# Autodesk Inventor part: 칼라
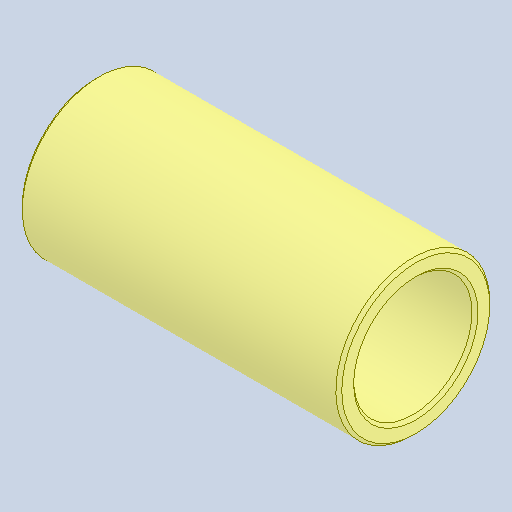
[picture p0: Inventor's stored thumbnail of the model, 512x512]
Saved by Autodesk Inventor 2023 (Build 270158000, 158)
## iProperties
Created: 2024-09
Part Number: 칼라
Material: 강철, 연강
Document SubType Name: Modeling
Designer: home
Density: 7.85 g/cm^3
Appearance: 기본값
Author: jhkim
Sending System: Autodesk Inventor 2025
Preprocessor: ST-DEVELOPER v20
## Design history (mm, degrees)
feature "솔리드1"
node "솔리드2"
